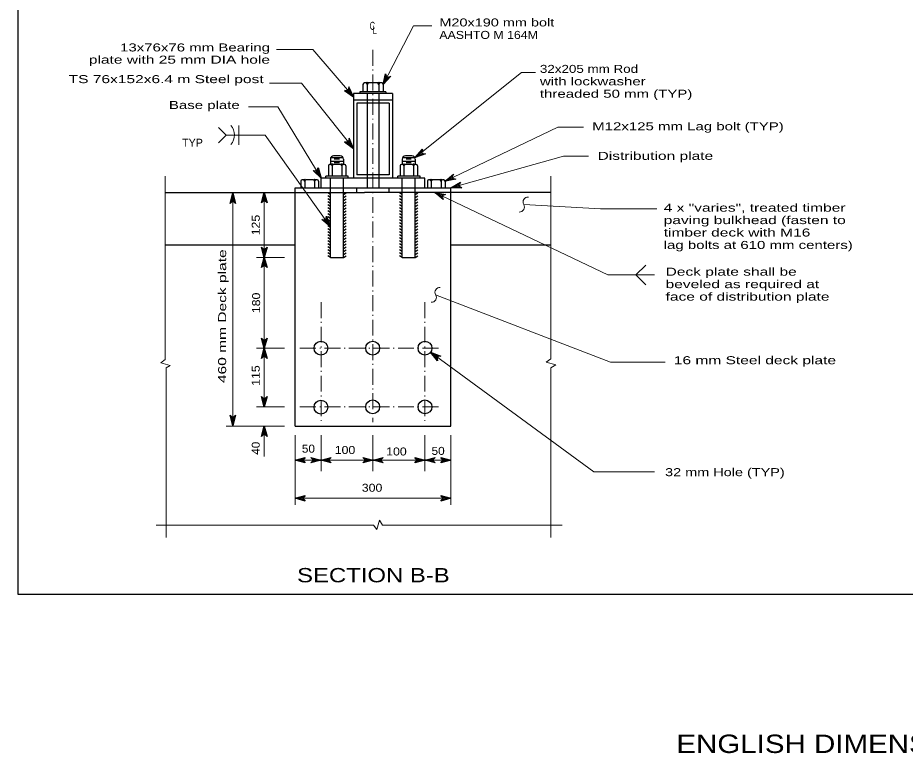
# Model space of a CAD drawing. Extents: x 13426 to 15509, y -9298 to -5111.
# Drawn here: x 15181.1 to 15326, y -5349.3 to -5229.2 of the extents above; entities that cross this region are included whole.
import ezdxf
from ezdxf.enums import TextEntityAlignment as Align

# ---------------------------------------------------------------- set-up
doc = ezdxf.new("R2010")
doc.units = 0
doc.header["$LTSCALE"] = 0.52
doc.header["$PDMODE"] = 32
doc.header["$PDSIZE"] = 0.26
doc.linetypes.add('DOT_DASHED', pattern=[7.7, 5, -1.2, 0.3, -1.2])
doc.linetypes.add('LONG_DASHED', pattern=[7.5, 6, -1.5])
for name, color, linetype, lineweight in [('1', 7, 'Continuous', 13), ('15', 7, 'Continuous', 13), ('16', 7, 'Continuous', 25), ('20', 7, 'Continuous', 13), ('3', 7, 'Continuous', 25), ('30', 7, 'Continuous', 25), ('4', 7, 'Continuous', 13), ('5', 7, 'Continuous', 25)]:
    doc.layers.add(name, color=color, linetype=linetype, lineweight=lineweight)
doc.layers.add('19', color=7, linetype='Continuous')

msp = doc.modelspace()

# ---------------------------------------------------------------- linework, layer by layer
at = {"layer": '1', "lineweight": 25}
for p, q in [((15226.397, -5295.877), (15226.397, -5256.938)), ((15226.397, -5256.938), (15251.846, -5256.938)), ((15251.846, -5295.877), (15251.846, -5256.938)), ((15205.196, -5257.735), (15237.718, -5257.735)), ((15268.144, -5257.735), (15240.553, -5257.735)), ((15205.196, -5266.233), (15226.397, -5266.233)), ((15251.846, -5266.233), (15268.144, -5266.233)), ((15226.397, -5295.877), (15251.846, -5295.877))]:
    msp.add_line(p, q, dxfattribs=at)
at = {"layer": '1', "linetype": 'LONG_DASHED', "lineweight": 25}
msp.add_line((15240.553, -5257.735), (15237.718, -5257.735), dxfattribs=at)
at = {"layer": '1'}
for points in [[(15205.196, -5284.967), (15204.468, -5285.522), (15206.003, -5285.947), (15205.325, -5286.346)], [(15268.144, -5284.879), (15267.416, -5285.434), (15268.95, -5285.859), (15268.144, -5286.333)], [(15239.218, -5312.016), (15239.773, -5312.744), (15240.198, -5311.209), (15240.672, -5312.016)]]:
    msp.add_lwpolyline(points, dxfattribs=at)
at = {"layer": '15'}
for p, q in [((15240.795, -5240.073), (15245.751, -5230.517)), ((15248.717, -5230.517), (15245.751, -5230.517)), ((15229.31, -5234.372), (15223.394, -5234.372)), ((15235.94, -5242.096), (15229.31, -5234.372)), ((15246.007, -5251.998), (15263.354, -5238.139)), ((15265.673, -5238.139), (15263.354, -5238.139)), ((15227.452, -5239.892), (15222.225, -5239.892)), ((15235.939, -5250.505), (15227.452, -5239.892)), ((15223.593, -5243.72), (15218.811, -5243.72)), ((15223.593, -5243.72), (15230.638, -5255.348)), ((15215.167, -5248.35), (15213.906, -5247.09)), ((15217.234, -5249.907), (15217.234, -5246.758)), ((15250.88, -5255.875), (15269.327, -5247.067)), ((15273.47, -5247.067), (15269.327, -5247.067)), ((15215.167, -5248.35), (15213.906, -5249.61)), ((15251.844, -5256.936), (15270.22, -5251.808)), ((15274.334, -5251.808), (15270.22, -5251.808)), ((15216.236, -5295.733), (15216.236, -5257.834)), ((15249.204, -5257.71), (15277.474, -5271.168)), ((15263.724, -5259.669), (15276.283, -5260.392)), ((15285.447, -5260.392), (15276.283, -5260.392)), ((15220.096, -5268.308), (15224.697, -5268.308)), ((15282.053, -5271.167), (15283.649, -5269.57)), ((15277.474, -5271.168), (15285.101, -5271.168)), ((15282.053, -5271.167), (15283.649, -5272.763)), ((15249.35, -5274.414), (15277.923, -5285.39)), ((15220.096, -5283.153), (15224.697, -5283.153)), ((15248.519, -5283.796), (15275.155, -5303.294)), ((15286.809, -5285.39), (15277.923, -5285.39)), ((15220.096, -5292.697), (15224.697, -5292.697)), ((15215.161, -5295.877), (15224.697, -5295.877)), ((15221.372, -5295.877), (15221.372, -5300.823)), ((15221.372, -5295.877), (15221.372, -5300.823)), ((15226.397, -5297.304), (15226.397, -5308.713)), ((15230.638, -5303.221), (15230.638, -5297.304)), ((15239.121, -5297.304), (15239.121, -5303.221)), ((15247.604, -5297.304), (15247.604, -5303.221)), ((15251.846, -5297.304), (15251.846, -5308.713)), ((15275.155, -5303.294), (15285.101, -5303.294)), ((15226.397, -5307.638), (15251.846, -5307.638))]:
    msp.add_line(p, q, dxfattribs=at)
at = {"layer": '15', "linetype": 'DOT_DASHED'}
for p, q in [((15239.121, -5234.435), (15239.121, -5295.222)), ((15230.638, -5275.615), (15230.638, -5295.222)), ((15247.604, -5275.615), (15247.604, -5295.222)), ((15227.196, -5283.153), (15250.225, -5283.153)), ((15227.196, -5292.697), (15250.225, -5292.697))]:
    msp.add_line(p, q, dxfattribs=at)
at = {"layer": '15', "lineweight": 25}
for p, q in [((15232.169, -5252.25), (15232.169, -5253.149)), ((15234.29, -5252.25), (15234.29, -5253.148)), ((15243.893, -5252.253), (15243.893, -5253.151)), ((15246.013, -5252.253), (15246.013, -5253.151)), ((15232.169, -5268.305), (15232.169, -5255.345)), ((15234.29, -5268.305), (15234.29, -5255.345)), ((15243.893, -5268.308), (15243.893, -5255.348)), ((15246.014, -5268.308), (15246.014, -5255.348))]:
    msp.add_line(p, q, dxfattribs=at)
at = {"layer": '15'}
for points in [[(15232.145, -5263.266), (15221.531, -5248.35), (15215.167, -5248.35)], [(15221.372, -5292.697), (15221.372, -5283.153), (15221.372, -5268.308), (15221.372, -5257.735)], [(15226.397, -5301.411), (15230.638, -5301.411), (15239.121, -5301.411), (15247.604, -5301.411), (15251.846, -5301.411)]]:
    msp.add_lwpolyline(points, dxfattribs=at)
for centre, radius, start, end in [((15214.023, -5248.3211), 2.4654, 320.64412, 39.35587), ((15264.4143, -5259.2659), 0.7991, 84.81118, 210.28192), ((15263.0511, -5260.0995), 0.7991, 267.14511, 32.61584), ((15250.0399, -5274.0106), 0.7991, 84.81118, 210.28192), ((15248.6768, -5274.8443), 0.7991, 267.14511, 32.61584)]:
    msp.add_arc(centre, radius, start, end, dxfattribs=at)
at = {"layer": '16'}
for points in [[(15241.64, -5238.861), (15242.014, -5238.75), (15240.795, -5240.073), (15241.174, -5238.315), (15241.3, -5238.684), (15240.795, -5240.073), (15241.64, -5238.861), (15241.382, -5238.943), (15241.3, -5238.684)], [(15234.841, -5241.108), (15234.451, -5241.087), (15235.94, -5242.096), (15235.169, -5240.471), (15235.131, -5240.86), (15235.94, -5242.096), (15234.841, -5241.108), (15235.111, -5241.129), (15235.131, -5240.86)], [(15234.875, -5249.48), (15234.485, -5249.446), (15235.939, -5250.505), (15235.224, -5248.854), (15235.173, -5249.242), (15235.939, -5250.505), (15234.875, -5249.48), (15235.143, -5249.51), (15235.173, -5249.242)], [(15247.327, -5251.335), (15247.709, -5251.417), (15246.007, -5251.998), (15247.179, -5250.633), (15247.113, -5251.018), (15246.007, -5251.998), (15247.327, -5251.335), (15247.062, -5251.284), (15247.113, -5251.018)], [(15230.043, -5253.996), (15230.144, -5253.618), (15230.638, -5255.348), (15229.335, -5254.109), (15229.715, -5254.194), (15230.638, -5255.348), (15230.043, -5253.996), (15229.978, -5254.259), (15229.715, -5254.194)], [(15252.285, -5255.417), (15252.65, -5255.554), (15250.88, -5255.875), (15252.242, -5254.7), (15252.12, -5255.071), (15250.88, -5255.875), (15252.285, -5255.417), (15252.029, -5255.326), (15252.12, -5255.071)], [(15253.307, -5256.727), (15253.643, -5256.925), (15251.844, -5256.936), (15253.389, -5256.014), (15253.204, -5256.358), (15251.844, -5256.936), (15253.307, -5256.727), (15253.071, -5256.594), (15253.204, -5256.358)], [(15216.052, -5259.24), (15215.781, -5259.5), (15216.236, -5257.834), (15216.69, -5259.5), (15216.419, -5259.24), (15216.236, -5257.834), (15216.052, -5259.24), (15216.236, -5259.056), (15216.419, -5259.24)], [(15221.189, -5259.141), (15220.918, -5259.401), (15221.372, -5257.735), (15221.827, -5259.401), (15221.557, -5259.141), (15221.372, -5257.735), (15221.189, -5259.141), (15221.372, -5258.957), (15221.557, -5259.141)], [(15250.444, -5258.513), (15250.567, -5258.883), (15249.204, -5257.71), (15250.974, -5258.029), (15250.609, -5258.167), (15249.204, -5257.71), (15250.444, -5258.513), (15250.354, -5258.257), (15250.609, -5258.167)], [(15231.452, -5261.962), (15231.524, -5261.578), (15232.145, -5263.266), (15230.753, -5262.127), (15231.14, -5262.184), (15232.145, -5263.266), (15231.452, -5261.962), (15231.407, -5262.229), (15231.14, -5262.184)], [(15221.557, -5266.902), (15221.827, -5266.642), (15221.372, -5268.308), (15220.918, -5266.642), (15221.189, -5266.902), (15221.372, -5268.308), (15221.557, -5266.902), (15221.372, -5267.086), (15221.189, -5266.902)], [(15221.189, -5269.714), (15220.918, -5269.973), (15221.372, -5268.308), (15221.827, -5269.973), (15221.557, -5269.714), (15221.372, -5268.308), (15221.189, -5269.714), (15221.372, -5269.53), (15221.557, -5269.714)], [(15221.557, -5281.747), (15221.827, -5281.488), (15221.372, -5283.153), (15220.918, -5281.488), (15221.189, -5281.747), (15221.372, -5283.153), (15221.557, -5281.747), (15221.372, -5281.931), (15221.189, -5281.747)], [(15221.189, -5284.559), (15220.918, -5284.819), (15221.372, -5283.153), (15221.827, -5284.819), (15221.557, -5284.559), (15221.372, -5283.153), (15221.189, -5284.559), (15221.372, -5284.375), (15221.557, -5284.559)], [(15249.588, -5284.816), (15249.64, -5285.202), (15248.519, -5283.796), (15250.198, -5284.439), (15249.814, -5284.507), (15248.519, -5283.796), (15249.588, -5284.816), (15249.546, -5284.548), (15249.814, -5284.507)], [(15221.557, -5291.291), (15221.827, -5291.031), (15221.372, -5292.697), (15220.918, -5291.031), (15221.189, -5291.291), (15221.372, -5292.697), (15221.557, -5291.291), (15221.372, -5291.474), (15221.189, -5291.291)], [(15216.419, -5294.327), (15216.69, -5294.067), (15216.236, -5295.733), (15215.781, -5294.067), (15216.052, -5294.327), (15216.236, -5295.733), (15216.419, -5294.327), (15216.236, -5294.511), (15216.052, -5294.327)], [(15221.189, -5297.283), (15220.918, -5297.543), (15221.372, -5295.877), (15221.827, -5297.543), (15221.557, -5297.283), (15221.372, -5295.877), (15221.189, -5297.283), (15221.372, -5297.1), (15221.557, -5297.283)], [(15227.803, -5301.595), (15228.062, -5301.866), (15226.397, -5301.411), (15228.062, -5300.957), (15227.803, -5301.227), (15226.397, -5301.411), (15227.803, -5301.595), (15227.619, -5301.411), (15227.803, -5301.227)], [(15229.232, -5301.227), (15228.973, -5300.957), (15230.638, -5301.411), (15228.973, -5301.866), (15229.232, -5301.595), (15230.638, -5301.411), (15229.232, -5301.227), (15229.416, -5301.411), (15229.232, -5301.595)], [(15232.044, -5301.595), (15232.304, -5301.866), (15230.638, -5301.411), (15232.304, -5300.957), (15232.044, -5301.227), (15230.638, -5301.411), (15232.044, -5301.595), (15231.86, -5301.411), (15232.044, -5301.227)], [(15237.715, -5301.227), (15237.455, -5300.957), (15239.121, -5301.411), (15237.455, -5301.866), (15237.715, -5301.595), (15239.121, -5301.411), (15237.715, -5301.227), (15237.899, -5301.411), (15237.715, -5301.595)], [(15240.527, -5301.595), (15240.787, -5301.866), (15239.121, -5301.411), (15240.787, -5300.957), (15240.527, -5301.227), (15239.121, -5301.411), (15240.527, -5301.595), (15240.343, -5301.411), (15240.527, -5301.227)], [(15246.198, -5301.227), (15245.939, -5300.957), (15247.604, -5301.411), (15245.939, -5301.866), (15246.198, -5301.595), (15247.604, -5301.411), (15246.198, -5301.227), (15246.382, -5301.411), (15246.198, -5301.595)], [(15249.01, -5301.595), (15249.27, -5301.866), (15247.604, -5301.411), (15249.27, -5300.957), (15249.01, -5301.227), (15247.604, -5301.411), (15249.01, -5301.595), (15248.827, -5301.411), (15249.01, -5301.227)], [(15250.44, -5301.227), (15250.18, -5300.957), (15251.846, -5301.411), (15250.18, -5301.866), (15250.44, -5301.595), (15251.846, -5301.411), (15250.44, -5301.227), (15250.623, -5301.411), (15250.44, -5301.595)], [(15227.803, -5307.822), (15228.062, -5308.092), (15226.397, -5307.638), (15228.062, -5307.184), (15227.803, -5307.454), (15226.397, -5307.638), (15227.803, -5307.822), (15227.619, -5307.638), (15227.803, -5307.454)], [(15250.44, -5307.454), (15250.18, -5307.184), (15251.846, -5307.638), (15250.18, -5308.092), (15250.44, -5307.822), (15251.846, -5307.638), (15250.44, -5307.454), (15250.623, -5307.638), (15250.44, -5307.822)]]:
    msp.add_lwpolyline(points, dxfattribs=at)
at = {"layer": '3'}
for centre in [(15230.6251, -5283.1304), (15239.0699, -5283.1304), (15247.6098, -5283.1304), (15230.6251, -5292.758), (15239.0699, -5292.7118), (15247.6098, -5292.7118)]:
    msp.add_circle(centre, 1.1266, dxfattribs=at)
at = {"layer": '30'}
for p, q in [((15181.119, -5111.081), (15181.119, -5323.3)), ((15181.119, -5323.3), (15509.151, -5323.3))]:
    msp.add_line(p, q, dxfattribs=at)
at = {"layer": '4'}
for p, q in [((15205.196, -5255.063), (15205.196, -5284.967)), ((15268.144, -5255.063), (15268.144, -5284.879)), ((15205.325, -5314.02), (15205.325, -5286.346)), ((15268.144, -5314.028), (15268.144, -5286.333)), ((15203.72, -5312.016), (15239.218, -5312.016)), ((15240.672, -5312.016), (15270.006, -5312.016))]:
    msp.add_line(p, q, dxfattribs=at)
at = {"layer": '5'}
for p, q in [((15237.946, -5239.826), (15237.721, -5239.826)), ((15239.802, -5239.826), (15238.44, -5239.826)), ((15240.549, -5239.826), (15240.295, -5239.826)), ((15241.242, -5241.298), (15237, -5241.298)), ((15237, -5241.298), (15237, -5241.563)), ((15237.474, -5240.073), (15237.474, -5241.298)), ((15238.193, -5240.073), (15238.193, -5241.298)), ((15240.049, -5240.073), (15240.049, -5241.298)), ((15240.795, -5240.073), (15240.795, -5241.298)), ((15241.242, -5241.298), (15241.242, -5241.563)), ((15235.94, -5241.563), (15235.94, -5255.348)), ((15242.302, -5241.563), (15235.94, -5241.563)), ((15242.302, -5242.623), (15235.94, -5242.623)), ((15238.193, -5241.563), (15238.193, -5256.938)), ((15240.049, -5241.563), (15240.049, -5256.938)), ((15242.302, -5241.563), (15242.302, -5255.348)), ((15236.47, -5243.146), (15236.47, -5254.81)), ((15241.772, -5243.146), (15236.47, -5243.146)), ((15241.772, -5243.146), (15241.772, -5254.81)), ((15232.174, -5252.583), (15234.269, -5252.583)), ((15232.22, -5252.024), (15234.239, -5252.024)), ((15233.76, -5251.72), (15232.699, -5251.72)), ((15233.654, -5252.285), (15232.805, -5252.285)), ((15233.654, -5252.881), (15232.805, -5252.881)), ((15243.897, -5252.586), (15245.992, -5252.586)), ((15243.943, -5252.027), (15245.963, -5252.027)), ((15245.483, -5251.723), (15244.423, -5251.723)), ((15245.377, -5252.288), (15244.529, -5252.288)), ((15245.377, -5252.883), (15244.529, -5252.883)), ((15231.835, -5253.361), (15231.835, -5255.021)), ((15232.241, -5253.149), (15232.047, -5253.149)), ((15232.454, -5253.361), (15232.454, -5255.021)), ((15233.817, -5253.149), (15232.666, -5253.149)), ((15234.029, -5253.361), (15234.029, -5255.021)), ((15234.458, -5253.149), (15234.241, -5253.149)), ((15234.67, -5253.361), (15234.67, -5255.021)), ((15243.559, -5253.363), (15243.559, -5255.024)), ((15243.965, -5253.151), (15243.771, -5253.151)), ((15244.177, -5253.363), (15244.177, -5255.024)), ((15245.54, -5253.151), (15244.389, -5253.151)), ((15245.752, -5253.363), (15245.752, -5255.024)), ((15246.181, -5253.151), (15245.964, -5253.151)), ((15246.394, -5253.363), (15246.394, -5255.024)), ((15227.759, -5255.66), (15227.564, -5255.66)), ((15229.37, -5255.66), (15228.188, -5255.66)), ((15230.018, -5255.66), (15229.798, -5255.66)), ((15230.638, -5256.938), (15230.638, -5255.348)), ((15231.434, -5255.348), (15231.434, -5255.039)), ((15241.772, -5254.81), (15236.47, -5254.81)), ((15243.156, -5255.35), (15243.156, -5255.042)), ((15248.407, -5255.66), (15248.212, -5255.66)), ((15250.018, -5255.66), (15248.836, -5255.66)), ((15250.666, -5255.66), (15250.446, -5255.66)), ((15227.349, -5255.875), (15227.349, -5256.938)), ((15227.974, -5255.875), (15227.974, -5256.938)), ((15229.585, -5255.875), (15229.585, -5256.938)), ((15230.233, -5255.875), (15230.233, -5256.938)), ((15236.47, -5257.735), (15236.47, -5256.938)), ((15241.772, -5257.735), (15241.772, -5256.938)), ((15247.997, -5255.875), (15247.997, -5256.938)), ((15248.622, -5255.875), (15248.622, -5256.938)), ((15250.233, -5255.875), (15250.233, -5256.938)), ((15250.881, -5255.875), (15250.881, -5256.938)), ((15232.17, -5258.02), (15231.73, -5257.766)), ((15232.17, -5258.51), (15231.73, -5258.256)), ((15234.29, -5258.02), (15234.73, -5257.766)), ((15234.29, -5258.51), (15234.73, -5258.256)), ((15243.893, -5258.023), (15243.453, -5257.769)), ((15243.893, -5258.513), (15243.453, -5258.259)), ((15246.013, -5258.023), (15246.453, -5257.769)), ((15246.013, -5258.513), (15246.453, -5258.259)), ((15232.17, -5259), (15231.73, -5258.746)), ((15232.17, -5259.49), (15231.73, -5259.236)), ((15232.17, -5259.979), (15231.73, -5259.725)), ((15234.29, -5259), (15234.73, -5258.746)), ((15234.29, -5259.49), (15234.73, -5259.236)), ((15234.29, -5259.979), (15234.73, -5259.725)), ((15243.893, -5259.002), (15243.453, -5258.749)), ((15243.893, -5259.492), (15243.453, -5259.238)), ((15243.893, -5259.982), (15243.453, -5259.728)), ((15246.013, -5259.002), (15246.453, -5258.749)), ((15246.013, -5259.492), (15246.453, -5259.238)), ((15246.013, -5259.982), (15246.453, -5259.728)), ((15232.17, -5260.469), (15231.73, -5260.215)), ((15232.17, -5260.959), (15231.73, -5260.705)), ((15232.17, -5261.449), (15231.73, -5261.195)), ((15234.29, -5260.469), (15234.73, -5260.215)), ((15234.29, -5260.959), (15234.73, -5260.705)), ((15234.29, -5261.449), (15234.73, -5261.195)), ((15243.893, -5260.472), (15243.453, -5260.218)), ((15243.893, -5260.962), (15243.453, -5260.707)), ((15243.893, -5261.451), (15243.453, -5261.197)), ((15246.013, -5260.472), (15246.453, -5260.218)), ((15246.013, -5260.962), (15246.453, -5260.707)), ((15246.013, -5261.451), (15246.453, -5261.197)), ((15232.17, -5261.938), (15231.73, -5261.685)), ((15232.17, -5262.428), (15231.73, -5262.174)), ((15232.17, -5262.918), (15231.73, -5262.664)), ((15234.29, -5261.938), (15234.73, -5261.685)), ((15234.29, -5262.428), (15234.73, -5262.174)), ((15234.29, -5262.918), (15234.73, -5262.664)), ((15243.893, -5261.941), (15243.453, -5261.687)), ((15243.893, -5262.431), (15243.453, -5262.177)), ((15243.893, -5262.921), (15243.453, -5262.667)), ((15246.013, -5261.941), (15246.453, -5261.687)), ((15246.013, -5262.431), (15246.453, -5262.177)), ((15246.013, -5262.921), (15246.453, -5262.667)), ((15232.17, -5263.408), (15231.73, -5263.154)), ((15232.17, -5263.898), (15231.73, -5263.644)), ((15232.17, -5264.387), (15231.73, -5264.133)), ((15234.29, -5263.408), (15234.73, -5263.154)), ((15234.29, -5263.898), (15234.73, -5263.644)), ((15234.29, -5264.387), (15234.73, -5264.133)), ((15243.893, -5263.411), (15243.453, -5263.156)), ((15243.893, -5263.9), (15243.453, -5263.646)), ((15243.893, -5264.39), (15243.453, -5264.136)), ((15246.013, -5263.411), (15246.453, -5263.156)), ((15246.013, -5263.9), (15246.453, -5263.646)), ((15246.013, -5264.39), (15246.453, -5264.136)), ((15232.17, -5264.877), (15231.73, -5264.623)), ((15232.17, -5265.367), (15231.73, -5265.113)), ((15232.17, -5265.857), (15231.73, -5265.603)), ((15234.29, -5264.877), (15234.73, -5264.623)), ((15234.29, -5265.367), (15234.73, -5265.113)), ((15234.29, -5265.857), (15234.73, -5265.603)), ((15243.893, -5264.88), (15243.453, -5264.626)), ((15243.893, -5265.369), (15243.453, -5265.115)), ((15243.893, -5265.859), (15243.453, -5265.605)), ((15246.013, -5264.88), (15246.453, -5264.626)), ((15246.013, -5265.369), (15246.453, -5265.115)), ((15246.013, -5265.859), (15246.453, -5265.605)), ((15232.17, -5266.346), (15231.73, -5266.092)), ((15232.17, -5266.836), (15231.73, -5266.582)), ((15232.17, -5267.326), (15231.73, -5267.072)), ((15234.29, -5266.346), (15234.73, -5266.092)), ((15234.29, -5266.836), (15234.73, -5266.582)), ((15234.29, -5267.326), (15234.73, -5267.072)), ((15243.893, -5266.349), (15243.453, -5266.095)), ((15243.893, -5266.839), (15243.453, -5266.585)), ((15243.893, -5267.328), (15243.453, -5267.075)), ((15246.013, -5266.349), (15246.453, -5266.095)), ((15246.013, -5266.839), (15246.453, -5266.585)), ((15246.013, -5267.328), (15246.453, -5267.075)), ((15232.17, -5267.815), (15231.73, -5267.562)), ((15232.169, -5268.305), (15231.73, -5268.051)), ((15232.169, -5268.305), (15234.29, -5268.305)), ((15234.29, -5267.815), (15234.73, -5267.562)), ((15234.29, -5268.305), (15234.73, -5268.051)), ((15243.893, -5267.818), (15243.453, -5267.564)), ((15243.893, -5268.308), (15243.453, -5268.054)), ((15243.893, -5268.308), (15246.014, -5268.308)), ((15246.013, -5267.818), (15246.453, -5267.564)), ((15246.014, -5268.308), (15246.453, -5268.054))]:
    msp.add_line(p, q, dxfattribs=at)
for points in [[(15247.604, -5256.938), (15247.604, -5255.348), (15230.638, -5255.348)], [(15235.079, -5255.348), (15235.079, -5255.039), (15231.434, -5255.039)], [(15246.802, -5255.35), (15246.802, -5255.042), (15243.156, -5255.042)]]:
    msp.add_lwpolyline(points, dxfattribs=at)
for centre, radius, start, end in [((15237.7207, -5240.0728), 0.2468, 90, 179.99999), ((15237.9465, -5240.0728), 0.2468, 0, 90), ((15238.4401, -5240.0728), 0.2468, 90, 179.99999), ((15239.802, -5240.0728), 0.2468, 0, 90), ((15240.2955, -5240.0728), 0.2468, 90, 179.99999), ((15240.5485, -5240.0728), 0.2468, 0, 90), ((15232.6995, -5252.2506), 0.5302, 90, 179.99999), ((15233.7598, -5252.2506), 0.5302, 0, 90), ((15244.4226, -5252.2532), 0.5302, 90, 179.99999), ((15245.483, -5252.2532), 0.5302, 0, 90), ((15232.0476, -5253.3608), 0.2121, 90, 179.99999), ((15232.2416, -5253.3608), 0.2121, 0, 90), ((15232.6658, -5253.3608), 0.2121, 90, 179.99999), ((15233.8166, -5253.3608), 0.2121, 0, 90), ((15234.2407, -5253.3608), 0.2121, 90, 179.99999), ((15234.4581, -5253.3608), 0.2121, 0, 90), ((15243.7708, -5253.3634), 0.2121, 90, 179.99999), ((15243.9648, -5253.3634), 0.2121, 0, 90), ((15244.389, -5253.3634), 0.2121, 90, 179.99999), ((15245.5397, -5253.3634), 0.2121, 0, 90), ((15245.9639, -5253.3634), 0.2121, 90, 179.99999), ((15246.1813, -5253.3634), 0.2121, 0, 90), ((15227.5633, -5255.8749), 0.2142, 90, 179.99999), ((15227.7593, -5255.8749), 0.2142, 0, 90), ((15228.1878, -5255.8749), 0.2142, 90, 179.99999), ((15229.3701, -5255.8749), 0.2142, 0, 90), ((15229.7985, -5255.8749), 0.2142, 90, 179.99999), ((15230.0181, -5255.8749), 0.2142, 0, 90), ((15248.2114, -5255.8749), 0.2142, 90, 179.99999), ((15248.4074, -5255.8749), 0.2142, 0, 90), ((15248.8359, -5255.8749), 0.2142, 90, 179.99999), ((15250.0182, -5255.8749), 0.2142, 0, 90), ((15250.4467, -5255.8749), 0.2142, 90, 179.99999), ((15250.6662, -5255.8749), 0.2142, 0, 90)]:
    msp.add_arc(centre, radius, start, end, dxfattribs=at)
for p in [(15238.188, -5239.826), (15240.049, -5239.826), (15232.454, -5253.149), (15234.029, -5253.149), (15244.177, -5253.151), (15245.752, -5253.151), (15227.969, -5255.66), (15229.585, -5255.66), (15248.617, -5255.66), (15250.233, -5255.66)]:
    msp.add_point(p, dxfattribs=at)

# ---------------------------------------------------------------- texts
at = {"layer": '1', "width": 1.2}
msp.add_text('ENGLISH DIMENSIONS ARE SHOWN ON LEVEL 21', height=3, dxfattribs=at).set_placement((15288.661, -5349.212))
at = {"layer": '19'}
for s, width, p in [('M20x190 mm bolt', 1.35, (15249.961, -5230.606)), ('AASHTO M 164M', 1.15, (15249.961, -5232.642)), ('32x205 mm Rod', 1.25, (15266.378, -5238.188)), ('with lockwasher', 1.4, (15266.378, -5240.216)), ('threaded 50 mm (TYP)', 1.4, (15266.378, -5242.244)), ('M12x125 mm Lag bolt (TYP)', 1.4, (15274.913, -5247.561)), ('4 x "varies", treated timber', 1.45, (15286.588, -5260.846)), ('paving bulkhead (fasten to', 1.45, (15286.588, -5262.874)), ('timber deck with M16', 1.45, (15286.588, -5264.902)), ('lag bolts at 610 mm centers)', 1.4, (15286.588, -5266.93)), ('16 mm Steel deck plate', 1.45, (15288.244, -5285.747)), ('32 mm Hole (TYP)', 1.35, (15286.816, -5304.022))]:
    msp.add_text(s, height=1.307, dxfattribs=dict(at, width=width)).set_placement(p)
for s, width, p in [('13x76x76 mm Bearing', 1.4, (15222.306, -5234.688)), ('plate with 25 mm DIA hole', 1.45, (15222.305, -5236.682)), ('TS 76x152x6.4 m Steel post', 1.45, (15221.268, -5239.861))]:
    msp.add_text(s, height=1.307, dxfattribs=dict(at, width=width)).set_placement(p, align=Align.RIGHT)
for s, width, p in [('125', 1.15, (15220.633, -5263.031)), ('460 mm Deck plate', 1.45, (15215.146, -5277.9075)), ('180', 1.15, (15220.694, -5275.735)), ('115', 1.15, (15220.628, -5287.599)), ('40', 1.1, (15220.632, -5299.4645))]:
    msp.add_text(s, height=1.307, rotation=90, dxfattribs=dict(at, width=width)).set_placement(p, align=Align.CENTER)
for s, width, p in [('50', 1.1, (15228.5785, -5300.184)), ('100', 1.15, (15234.555, -5300.404)), ('50', 1.1, (15249.7545, -5300.55)), ('100', 1.15, (15242.95, -5300.648)), ('300', 1.15, (15238.972, -5306.565)), ('300', 1.15, (15238.972, -5306.565))]:
    msp.add_text(s, height=1.307, dxfattribs=dict(at, width=width)).set_placement(p, align=Align.CENTER)
at = {"layer": '20'}
for s, height, width, p in [('C', 1.307, 0.65, (15239.0145, -5231.154)), ('L', 1.307, 0.75, (15239.3835, -5231.796)), ('SECTION B-B', 2.333, 1.25, (15239.187, -5321.35))]:
    msp.add_text(s, height=height, dxfattribs=dict(at, width=width)).set_placement(p, align=Align.CENTER)
at = {"layer": '20', "width": 1.4}
msp.add_text('Base plate', height=1.307, dxfattribs=at).set_placement((15217.364, -5244.086), align=Align.RIGHT)
at = {"layer": '20'}
msp.add_text('TYP', height=1.307, dxfattribs=at).set_placement((15211.347, -5250.242), align=Align.RIGHT)
at = {"layer": '20', "width": 1.45}
for s, p in [('Distribution plate', (15275.793, -5252.383)), ('Deck plate shall be', (15286.897, -5271.293)), ('beveled as required at', (15286.897, -5273.329)), ('face of distribution plate', (15286.897, -5275.366))]:
    msp.add_text(s, height=1.307, dxfattribs=at).set_placement(p)

doc.saveas('drawing.dxf')
